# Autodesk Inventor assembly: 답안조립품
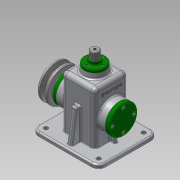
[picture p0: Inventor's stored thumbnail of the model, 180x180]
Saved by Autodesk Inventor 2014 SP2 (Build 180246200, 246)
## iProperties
Created: 2016-08
Part Number: 답안조립품
Document SubType Name: Assembly
Designer: user
Author: user
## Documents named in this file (19)
- C:\Users\user\Desktop\460820V1021\답안조립품.iam
- C:\Users\user\Desktop\460820V1021\본체.ipt
- C:\Users\user\Desktop\460820V1021\뒤커버.ipt
- C:\Users\user\Desktop\460820V1021\베어링 15 x 35 x 11.ipt
- C:\Users\user\Desktop\460820V1021\상부부시.ipt
- C:\Users\user\Desktop\460820V1021\앞커버.ipt
- C:\Users\user\Desktop\460820V1021\오일실 15 25 7.ipt
- C:\Users\user\Desktop\460820V1021\링크.ipt
- C:\Users\user\Desktop\460820V1021\슬라이드바.ipt
- C:\Users\user\Desktop\460820V1021\편심축.ipt
- C:\Users\user\Desktop\460820V1021\멈춤링 15 x 1.ipt
- C:\Users\user\Desktop\460820V1021\멈춤링 6 x 5.ipt
- C:\Users\user\Desktop\460820V1021\고정핀.ipt
- C:\Users\user\Desktop\460820V1021\와셔.ipt
- C:\Users\user\Desktop\460820V1021\키 5 x 5 x 14.ipt
- C:\Users\user\Desktop\460820V1021\볼트 M3 x 8.ipt
- C:\Users\user\Desktop\460820V1021\볼트 M4 x 10.ipt
- C:\Users\user\Desktop\460820V1021\볼트 M6 x 12.ipt
- C:\Users\user\Desktop\460820V1021\V-벨트풀리.ipt
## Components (15 placed, 5 different names)
1. 고정핀:1 — 각도:4, 각도:5, 각도:6
2. ISO 4018 M6 x 12:1 — 강체:2
3. V-벨트풀리:1 — 각도:1
4. ISO 4762 M4 x 10:1 — 강체:3
5. ISO 4762 M4 x 10:3
6. ISO 4762 M4 x 10:4
7. ISO 4762 M4 x 10:5
8. ISO 4762 M4 x 10:2 — 강체:4
9. ISO 4762 M4 x 10:6
10. ISO 4762 M4 x 10:7
11. ISO 4762 M4 x 10:8
12. ISO 4762 M3 x 8:1 — 강체:5
13. ISO 4762 M3 x 8:2
14. ISO 4762 M3 x 8:3
15. ISO 4762 M3 x 8:4
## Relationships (8: WeldJoint 4, Angle 4)
- 강체:2 [WeldJoint]: ISO 4018 M6 x 12:1
- 각도:1 [Angle]: V-벨트풀리:1
- 강체:3 [WeldJoint]: ISO 4762 M4 x 10:1
- 강체:4 [WeldJoint]: ISO 4762 M4 x 10:2
- 강체:5 [WeldJoint]: ISO 4762 M3 x 8:1
- 각도:4 [Angle]: 고정핀:1
- 각도:5 [Angle]: 고정핀:1
- 각도:6 [Angle]: 고정핀:1
